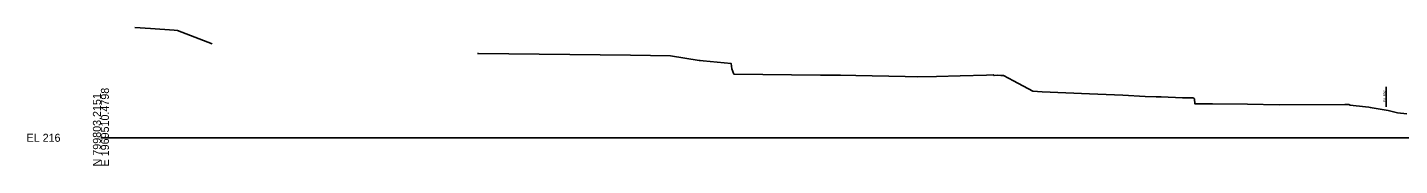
# Model space of a CAD drawing. Extents: x 1979833 to 1982361, y 790388 to 810009.
# Drawn here: x 1981332.9 to 1981812.8, y 794888 to 794936.3 of the extents above; entities that cross this region are included whole.
import ezdxf

# ---------------------------------------------------------------- set-up
doc = ezdxf.new("R2010")
doc.units = 0
for name, color, linetype in [('Default', 7, 'Continuous'), ('RD_GPK_XS_Cell', 7, 'Continuous'), ('RD_XS_ExGround', 7, 'Continuous'), ('RD_XS_ExRW', 7, 'Continuous')]:
    doc.layers.add(name, color=color, linetype=linetype)

msp = doc.modelspace()

# ---------------------------------------------------------------- linework, layer by layer
at = {"layer": 'RD_GPK_XS_Cell'}
msp.add_line((1981358.57, 794897.73), (1981858.57, 794897.73), dxfattribs=at)
at = {"layer": 'RD_XS_ExGround'}
for points in [[(1981370.46, 794936.29), (1981375.89, 794935.94), (1981384.15, 794935.3), (1981385.32, 794935.2), (1981397.49, 794930.57)], [(1981490.27, 794927.16), (1981490.7, 794927.18), (1981543.77, 794926.57), (1981557.79, 794926.37), (1981567.79, 794924.77), (1981568.24, 794924.71), (1981569.21, 794924.65), (1981579.07, 794923.66), (1981579.32, 794921.84), (1981579.97, 794920), (1981610.26, 794919.67), (1981617.3, 794919.64), (1981622.65, 794919.55), (1981639.93, 794919.14), (1981644.24, 794919.06), (1981650.84, 794919.19), (1981659.16, 794919.41), (1981668.31, 794919.63), (1981670.7, 794919.71), (1981671.02, 794919.55), (1981672.33, 794919.57), (1981673.41, 794919.55), (1981674.25, 794919.52), (1981677.81, 794917.59), (1981684.5, 794913.97), (1981687.78, 794913.81), (1981704.42, 794913.08), (1981715.98, 794912.58), (1981723.87, 794912.22), (1981727.69, 794912.05), (1981729.42, 794912.05), (1981736.94, 794911.71), (1981740.15, 794911.65), (1981740.49, 794911.64), (1981740.9, 794911.63), (1981741.08, 794911.34), (1981741.2, 794909.62), (1981743.29, 794909.59), (1981747.34, 794909.56), (1981759.69, 794909.52), (1981770.69, 794909.3), (1981793.69, 794909.41), (1981795.12, 794909.4), (1981795.28, 794909.2), (1981795.61, 794909.17), (1981800.91, 794908.54), (1981802.09, 794908.39), (1981802.6, 794908.33), (1981808.88, 794907.22), (1981812.11, 794906.47), (1981815.34, 794906.05)]]:
    msp.add_lwpolyline(points, dxfattribs=at)
at = {"layer": 'RD_XS_ExRW'}
msp.add_line((1981808.18, 794908.59), (1981808.18, 794915.59), dxfattribs=at)

# ---------------------------------------------------------------- texts
at = {"layer": 'Default'}
msp.add_text('-', height=0.0001, dxfattribs=at).set_placement((1981358.57, 794897.73))
msp.add_text('-', height=0.0001, dxfattribs=at).set_placement((1981358.57, 794897.73))
at = {"layer": 'RD_GPK_XS_Cell'}
for s, p in [('N 799803.2151', (1981358.57, 794887.73)), ('E 1969510.4798', (1981361.37, 794887.73))]:
    msp.add_text(s, height=2.8, rotation=90, dxfattribs=at).set_placement(p)
msp.add_text('EL 216', height=2.8, dxfattribs=at).set_placement((1981332.57, 794896.33))
at = {"layer": 'RD_XS_ExRW'}
msp.add_text('EX. R/W ', height=0.75, rotation=90, dxfattribs=at).set_placement((1981807.93, 794910.28))

doc.saveas('drawing.dxf')
